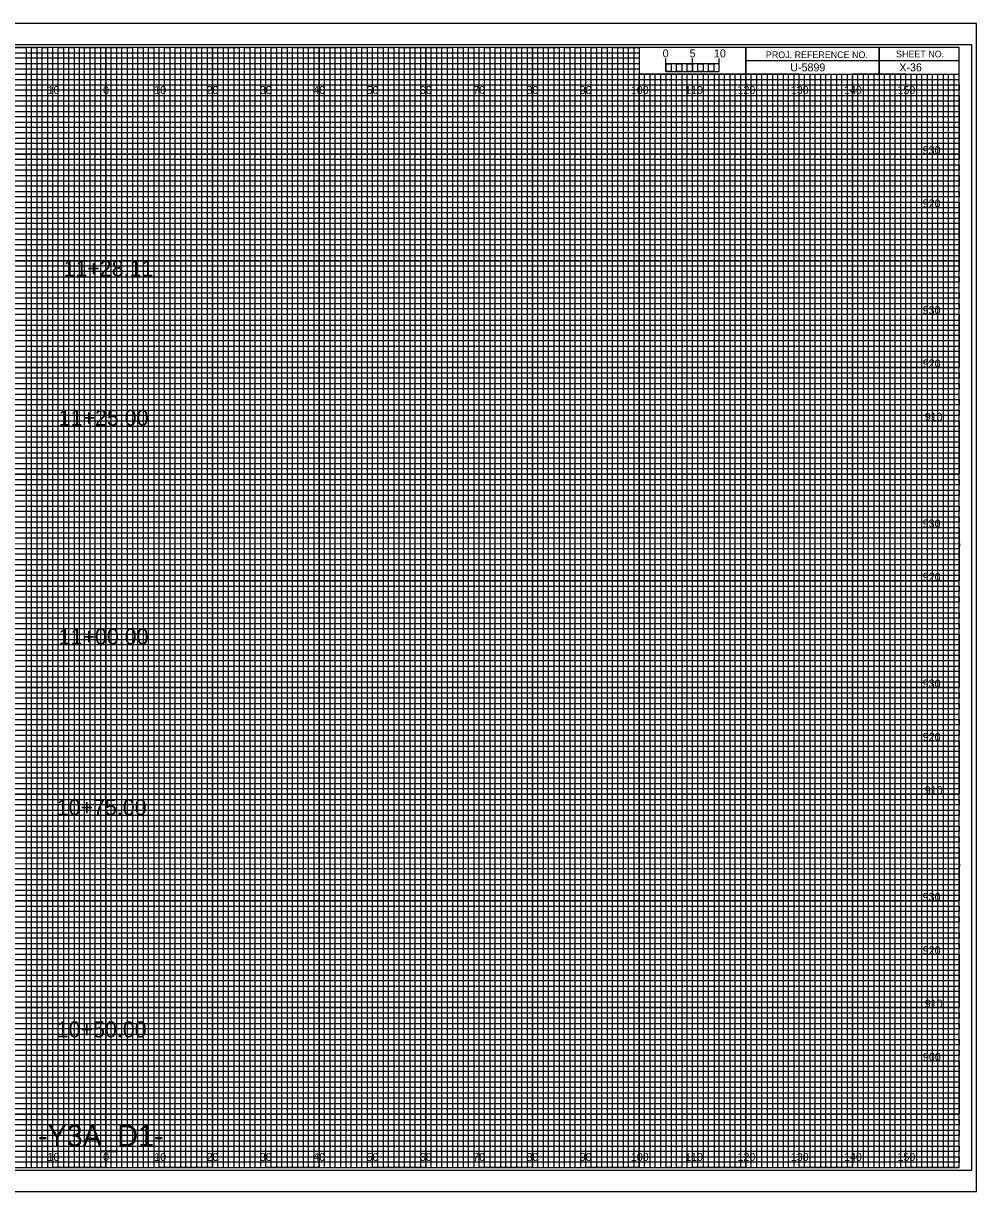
# Model space of a CAD drawing. Extents: x -13 to 323, y -4 to 214.
# Drawn here: x 144.5 to 323.3, y -4.5 to 214.5 of the extents above; entities that cross this region are included whole.
import ezdxf

# ---------------------------------------------------------------- set-up
doc = ezdxf.new("R2010")
doc.units = 0
for name, color, linetype in [('Prop XS Alignment Label', 7, 'Continuous'), ('Prop XS Bar Scale Labels', 7, 'Continuous'), ('Prop XS Elevation Labels', 7, 'Continuous'), ('Prop XS Offset Labels', 7, 'Continuous'), ('Prop XS Project Number', 7, 'Continuous'), ('Prop XS Sheet Number', 7, 'Continuous'), ('Prop XS Station Labels', 7, 'Continuous'), ('Sheet Cross Section CELL', 7, 'Continuous'), ('Sheet Cross Section Grid Major CELL', 7, 'Continuous'), ('Sheet Cross Section Grid Middle CELL', 7, 'Continuous'), ('Sheet Cross Section Grid Minor 1 CELL', 7, 'Continuous'), ('Sheet Cross Section Grid Minor 2 CELL', 7, 'Continuous'), ('Sheet Cross Section Scale CELL', 7, 'Continuous'), ('Sheet Cutting Line CELL', 7, 'Continuous'), ('Sheet DOT Grid CELL', 7, 'Continuous'), ('Sheet Plot Border Inside CELL', 7, 'Continuous'), ('Sheet Plot Border Outside CELL', 7, 'Continuous')]:
    doc.layers.add(name, color=color, linetype=linetype)

msp = doc.modelspace()

# ---------------------------------------------------------------- linework, layer by layer
at = {"layer": 'Sheet Cross Section CELL'}
for p, q in [((305, 210), (305, 205)), ((305, 205), (305, 210)), ((280, 207.5), (280, 205)), ((320, 207.49), (280, 207.49)), ((280, 205), (320, 205))]:
    msp.add_line(p, q, dxfattribs=at)
for points in [[(320, 210), (0, 210), (0, 0), (320, 0)], [(280, 210), (260, 210), (260, 205.03), (280, 205.03)], [(320, 210), (280, 210), (280, 205), (320, 205)]]:
    msp.add_lwpolyline(points, close=True, dxfattribs=at)
at = {"layer": 'Sheet Cross Section Grid Major CELL'}
for p, q in [((150, 210), (140, 210)), ((150, 0), (150, 210)), ((170, 210), (160, 210)), ((160, 210), (160, 0)), ((170, 0), (170, 210)), ((190, 210), (180, 210)), ((180, 210), (180, 0)), ((190, 0), (190, 210)), ((210, 210), (200, 210)), ((200, 210), (200, 0)), ((210, 0), (210, 210)), ((230, 210), (220, 210)), ((220, 210), (220, 0)), ((230, 0), (230, 210)), ((250, 210), (240, 210)), ((240, 210), (240, 0)), ((250, 0), (250, 210)), ((260, 210), (260, 0)), ((270, 0), (270, 205)), ((290, 205), (280, 205)), ((280, 205), (280, 0)), ((290, 0), (290, 205)), ((310, 205), (300, 205)), ((300, 205), (300, 0)), ((310, 0), (310, 205)), ((160, 0), (150, 0)), ((180, 0), (170, 0)), ((200, 0), (190, 0)), ((220, 0), (210, 0)), ((240, 0), (230, 0)), ((260, 0), (250, 0)), ((280, 0), (270, 0)), ((300, 0), (290, 0)), ((320, 0), (310, 0)), ((320, 0), (320, 0))]:
    msp.add_line(p, q, dxfattribs=at)
for points in [[(0, 200), (320, 200), (320, 190), (0, 190)], [(0, 180), (320, 180), (320, 170), (0, 170)], [(0, 160), (320, 160), (320, 150), (0, 150)], [(0, 140), (320, 140), (320, 130), (0, 130)], [(0, 120), (320, 120), (320, 110), (0, 110)], [(0, 100), (320, 100), (320, 90), (0, 90)], [(0, 80), (320, 80), (320, 70), (0, 70)], [(0, 60), (320, 60), (320, 50), (0, 50)], [(0, 40), (320, 40), (320, 30), (0, 30)], [(0, 20), (320, 20), (320, 10), (0, 10)]]:
    msp.add_lwpolyline(points, dxfattribs=at)
at = {"layer": 'Sheet Cross Section Grid Middle CELL'}
for points in [[(135, 210), (145, 210), (145, 0), (155, 0), (155, 210), (165, 210), (165, 0), (175, 0), (175, 210), (185, 210), (185, 0), (195, 0), (195, 210), (205, 210), (205, 0), (215, 0), (215, 210), (225, 210), (225, 0), (235, 0), (235, 210), (245, 210), (245, 0), (255, 0), (255, 210), (259.93, 210), (260, 210), (260, 205), (264.99, 205), (264.99, 0), (275, 0), (275, 205), (285, 205), (285, 0), (295, 0), (295, 205), (305, 205), (305, 0), (315, 0), (315, 205)], [(0, 205), (275, 205)], [(0, 185), (320, 185), (320, 195), (0, 195)], [(0, 165), (320, 165), (320, 175), (0, 175)], [(0, 145), (320, 145), (320, 155), (0, 155)], [(0, 125), (320, 125), (320, 135), (0, 135)], [(0, 105), (320, 105), (320, 115), (0, 115)], [(0, 85), (320, 85), (320, 95), (0, 95)], [(0, 65), (320, 65), (320, 75), (0, 75)], [(0, 45), (320, 45), (320, 55), (0, 55)], [(0, 25), (320, 25), (320, 35), (0, 35)], [(0, 5), (320, 5), (320, 15), (0, 15)]]:
    msp.add_lwpolyline(points, dxfattribs=at)
at = {"layer": 'Sheet Cross Section Grid Minor 1 CELL'}
for p, q in [((0, 209), (260, 209)), ((260, 209), (260, 207.98)), ((260, 207.98), (0, 207.98)), ((0, 207), (260, 207)), ((260, 205.89), (0, 205.89)), ((260, 207), (260, 205.89)), ((0, 204), (320, 204))]:
    msp.add_line(p, q, dxfattribs=at)
for points in [[(0, 203), (270, 203), (320, 203), (320, 202), (0, 202)], [(0, 201), (320, 201), (320, 199), (0, 199)], [(0, 198), (320, 198), (320, 197), (0, 196.98)], [(0, 196), (320, 196), (320, 194), (0, 194)], [(0, 193), (320, 193), (320, 192), (0, 192)], [(0, 191), (320, 191), (320, 189), (0, 189)], [(0, 188), (320, 188), (320, 187), (0, 187)], [(0, 186), (320, 186), (320, 184), (0, 184)], [(0, 183), (320, 183), (320, 182), (0, 182)], [(0, 181), (320, 181), (320, 179), (0, 179)], [(0, 178), (320, 178), (320, 177), (0, 177)], [(0, 176), (320, 176), (320, 173.95), (320, 173), (320, 172), (0, 172)], [(0, 174), (320, 174), (320, 173), (0, 173)], [(0, 171), (320, 171), (320, 169), (0, 169.03)], [(0, 169.03), (320, 169), (320, 168), (0, 168)], [(0, 167), (320, 167), (320, 166), (0, 166)], [(0, 164), (320, 164), (320, 163), (0, 163)], [(0, 162), (320, 162), (320, 161), (0, 161)], [(-0.07, 158.89), (320, 158.89), (320, 157.88), (-0.07, 157.88)], [(0, 157), (320, 157), (320, 156), (0, 156)], [(0, 154), (320, 154), (320, 153), (0, 153)], [(0, 152), (320, 152), (320, 151), (0, 151)], [(0, 149), (320, 149), (320, 148), (0, 148)], [(0, 147), (320, 147), (320, 146), (0, 146)], [(0, 144), (320, 144), (320, 143), (0, 143)], [(0, 142), (320, 142), (320, 141), (0, 141)], [(0, 139), (320, 139), (319.99, 137.98), (0, 138)], [(0, 137), (320, 137), (320, 136), (0, 136)], [(0, 134), (320, 134), (320, 133), (0, 133)], [(0, 132), (320, 132), (320, 131), (0, 131)], [(0, 129), (320, 129), (320, 128), (0, 128)], [(0, 127), (320, 127), (320, 126), (0, 126)], [(0, 124), (320, 124), (320, 123), (0, 123)], [(0, 122), (320, 122), (320, 121), (0, 121)], [(0, 119), (320, 119), (320, 118), (0, 118)], [(0, 116.99), (320.07, 116.91), (320, 116), (0, 116)], [(0, 114), (320, 114), (320, 113), (0, 113)], [(0, 112), (320, 112), (320, 111), (0, 111)], [(0, 109), (320, 109), (320, 108), (0, 108)], [(0, 107), (320, 107), (320, 106), (0, 106)], [(0, 104), (320, 104), (320, 103), (0, 103)], [(0, 102), (320, 102), (320, 101), (0, 101)], [(0, 99), (320, 99), (320, 98), (0, 98)], [(0, 97), (320, 97), (320, 96), (0, 96)], [(0, 94), (320, 94), (320, 93), (0, 93)], [(0, 92), (320, 92), (320, 91), (0, 91)], [(0, 89), (320, 89), (320, 88), (0, 88)], [(0, 87), (320, 87), (320, 86), (0, 86)], [(0, 84), (320, 84), (320, 83), (0, 83)], [(0, 82), (320, 82), (320, 81), (0, 81)], [(0, 79), (320, 79), (319.99, 77.98), (0, 78)], [(0, 77), (320, 77), (320, 76), (0, 76)], [(0, 74), (320, 74), (320, 73), (0, 73)], [(0, 72), (320, 72), (320, 71), (0, 71)], [(0, 69), (320, 69), (320, 68), (0, 68)], [(0, 67), (320, 67), (320, 66), (0, 66)], [(0, 64), (320, 64), (320, 63), (0, 63)], [(0, 62), (320, 62), (320, 61), (0, 61)], [(0, 59), (320, 59), (320, 58), (0, 58)], [(0, 56.99), (320.07, 56.91), (320, 56), (0, 56)], [(0, 54), (320, 54), (320, 53), (0, 53)], [(0, 52), (320, 52), (320, 51), (0, 51)], [(0, 49), (320, 49), (320, 48), (0, 48)], [(0, 47), (320, 47), (320, 46), (0, 46)], [(0, 44), (320, 44), (320, 43), (0, 43)], [(0, 42), (320, 42), (320, 41), (0, 41)], [(0, 39), (320, 39), (320, 38), (0, 38)], [(0, 37), (320, 37), (320, 36), (0, 36)], [(0, 34), (320, 34), (320, 33), (0, 33)], [(0, 32), (320, 32), (320, 31), (0, 31)], [(0, 29), (320, 29), (320, 28), (0, 28)], [(0, 27), (320, 27), (320, 26), (0, 26)], [(0, 24), (320, 24), (320, 23), (0, 23)], [(0, 22), (320, 22), (320, 21), (0, 21)], [(0, 19), (320, 19), (320, 18), (0, 18)], [(0, 17), (320, 17), (320, 16), (0, 16)], [(0, 14), (320, 14), (320, 13), (0, 13)], [(0, 12), (320, 12), (320, 11), (0, 11)], [(0, 9), (320, 9), (320, 8), (0, 8)], [(0, 7), (320, 7), (320, 6), (0, 6)], [(0, 4), (320, 4), (320, 3), (0, 3)], [(0, 2), (320, 2), (320, 1), (0, 1)]]:
    msp.add_lwpolyline(points, dxfattribs=at)
at = {"layer": 'Sheet Cross Section Grid Minor 2 CELL'}
for p, q in [((267, 205), (266.01, 205)), ((266.01, 205), (266.01, 0)), ((267, 0), (267, 205)), ((269, 205), (268, 205)), ((268, 205), (268, 0)), ((269, 0), (269, 205)), ((266.01, 0), (265, 0)), ((268, 0), (267, 0))]:
    msp.add_line(p, q, dxfattribs=at)
for points in [[(145, 0), (146, 0), (146, 210), (147, 210), (147, 0)], [(147, 0), (148, 0), (148, 210), (149, 210), (149, 0)], [(150, 0), (151, 0), (151, 210), (152, 210), (152, 0)], [(152, 0), (153, 0), (153, 210), (154, 210), (154, 0)], [(155, 0), (156, 0), (156, 210), (157, 210), (157, 0)], [(157, 0), (158, 0), (158, 210), (159, 210), (159, 0)], [(160, 0), (161, 0), (161, 210), (162, 210), (162, 0)], [(162, 0), (163, 0), (163, 210), (164, 210), (164, 0)], [(165, 0), (166, 0), (166, 210), (167, 210), (167, 0)], [(167, 0), (168, 0), (168, 210), (169, 210), (169, 0)], [(170, 0), (171, 0), (171, 210), (172, 210), (172, 0)], [(172, 0), (173, 0), (173, 210), (174, 210), (174, 0)], [(175, 0), (176, 0), (176, 210), (177, 210), (177, 0)], [(177, 0), (178, 0), (178, 210), (179, 210), (179, 0)], [(180, 0), (181, 0), (181, 210), (182, 210), (182, 0)], [(182, 0), (183, 0), (183, 210), (184, 210), (184, 0)], [(185, 0), (186, 0), (186, 210), (187, 210), (187, 0)], [(187, 0), (188, 0), (188, 210), (189, 210), (189, 0)], [(190, 0), (191, 0), (191, 210), (192, 210), (192, 0)], [(192, 0), (193, 0), (193, 210), (194, 210), (194, 0)], [(195, 0), (196, 0), (196, 210), (197, 210), (197, 0)], [(197, 0), (198, 0), (198, 210), (199, 210), (199, 0)], [(200, 0), (201, 0), (201, 210), (202, 210), (202, 0)], [(202, 0), (203, 0), (203, 210), (204, 210), (204, 0)], [(205, 0), (206, 0), (206, 210), (207, 210), (207, 0)], [(207, 0), (208, 0), (208, 210), (209, 210), (209, 0)], [(210, 0), (211, 0), (211, 210), (212, 210), (212, 0)], [(212, 0), (213, 0), (213, 210), (214, 210), (214, 0)], [(215, 0), (216, 0), (216, 210), (217, 210), (217, 0)], [(217, 0), (218, 0), (218, 210), (219, 210), (219, 0)], [(220, 0), (221, 0), (221, 210), (222, 210), (222, 0)], [(222, 0), (223, 0), (223, 210), (224, 210), (224, 0)], [(225, 0), (226, 0), (226, 210), (227, 210), (227, 0)], [(227, 0), (228, 0), (228, 210), (229, 210), (229, 0)], [(230, 0), (231, 0), (231, 210), (232, 210), (232, 0)], [(232, 0), (233, 0), (233, 210), (234, 210), (234, 0)], [(235, 0), (236, 0), (236, 210), (237, 210), (237, 0)], [(237, 0), (238, 0), (238, 210), (239, 210), (239, 0)], [(240, 0), (241, 0), (241, 210), (242, 210), (242, 0)], [(242, 0), (243, 0), (243, 210), (244, 210), (244, 0)], [(245, 0), (246, 0), (246, 210), (247, 210), (247, 0)], [(247, 0), (248, 0), (248, 210), (249, 210), (249, 0)], [(250, 0), (251, 0), (251, 210), (252, 210), (252, 0)], [(252, 0), (253, 0), (253, 210), (254, 210), (254, 0)], [(255, 0), (256, 0), (256, 210), (257, 210), (257, 0)], [(257, 0), (258, 0), (258, 210), (259, 210), (259, 0)], [(260, 0), (261, 0), (261, 205), (262.02, 205), (262.02, 0)], [(262, 0), (263, 0), (263, 205), (263.99, 205), (263.99, 0)], [(270, 0), (270.98, 0), (270.98, 205), (272, 205), (272, 0)], [(272, 0), (273, 0), (273, 205), (274.05, 205), (274.05, 0)], [(275, 0), (276, 0), (276, 205), (277, 205), (277, 0)], [(277, 0), (278, 0), (278, 205), (279, 205), (279, 0)], [(280, 0), (281, 0), (281, 205), (282, 205), (282, 0)], [(282, 0), (283, 0), (283, 205), (284, 205), (284, 0)], [(285, 0), (286, 0), (286, 205), (287, 205), (287, 0)], [(287, 0), (288, 0), (288, 205), (289, 205), (289, 0)], [(290, 0), (291, 0), (291, 205), (292, 205), (292, 0)], [(292, 0), (293, 0), (293, 205), (294, 205), (294, 0)], [(295, 0), (296, 0), (296, 205), (297, 205), (297, 0)], [(297, 0), (298, 0), (298, 205), (299, 205), (299, 0)], [(300, 0), (301, 0), (301, 205), (302, 205), (302, 0)], [(302, 0), (303, 0), (303, 205), (304, 205), (304, 0)], [(305, 0), (306, 0), (306, 205), (307, 205), (307, 0)], [(307, 0), (308, 0), (308, 205), (309, 205), (309, 0)], [(310, 0), (311, 0), (311, 205), (312, 205), (312, 0)], [(312, 0), (313, 0), (313, 205), (314, 205), (314, 0)], [(315, 0), (316, 0), (316, 205), (317, 205), (317, 0)], [(317, 0), (318, 0), (318, 205), (319, 205), (319, 0)]]:
    msp.add_lwpolyline(points, dxfattribs=at)
at = {"layer": 'Sheet Cross Section Scale CELL'}
for p, q in [((265, 205.49), (265, 207.9)), ((265, 206.9), (265, 207.9)), ((270, 205.49), (270, 207.9)), ((275, 205.49), (275, 207.9)), ((275, 206.9), (275, 207.9))]:
    msp.add_line(p, q, dxfattribs=at)
for points in [[(275, 206.9), (265, 206.9), (265, 205.49), (275, 205.49)], [(265, 206.9), (266, 206.9), (266, 205.49), (265, 205.49)], [(267, 206.9), (268, 206.9), (268, 205.49), (267, 205.49)], [(269, 206.9), (270, 206.9), (270, 205.49), (269, 205.49)], [(271, 206.9), (272, 206.9), (272, 205.49), (271, 205.49)], [(273, 206.9), (274, 206.9), (274, 205.49), (273, 205.49)]]:
    msp.add_lwpolyline(points, close=True, dxfattribs=at)
at = {"layer": 'Sheet Cutting Line CELL'}
for p, q in [((323.3, 214.5), (-13.4, 214.5)), ((-13.4, -4.5), (323.3, -4.5))]:
    msp.add_line(p, q, dxfattribs=at)
at = {"layer": 'Sheet DOT Grid CELL'}
for p, q in [((150, 0), (150, 210)), ((160, 0), (160, 210)), ((170, 0), (170, 210)), ((180, 0), (180, 210)), ((190, 0), (190, 210)), ((200, 0), (200, 210)), ((210, 0), (210, 210)), ((220, 0), (220, 210)), ((230, 0), (230, 210)), ((240, 0), (240, 210)), ((250, 0), (250, 210)), ((260, 0), (260, 204.69)), ((270, 0), (270, 204.69)), ((280, 0), (280, 204.69)), ((290, 0), (290, 204.69)), ((300, 0), (300, 204.69)), ((310, 0), (310, 204.69)), ((0, 200), (320, 200)), ((0, 190), (320, 190)), ((0, 180), (320, 180)), ((0, 170), (320, 170)), ((0, 160), (320, 160)), ((0, 150), (320, 150)), ((0, 140), (320, 140)), ((0, 130), (320, 130)), ((0, 120), (320, 120)), ((0, 110), (320, 110)), ((0, 100), (320, 100)), ((0, 90), (320, 90)), ((0, 80), (320, 80)), ((0, 70), (320, 70)), ((0, 60), (320, 60)), ((0, 50), (320, 50)), ((0, 40), (320, 40)), ((0, 30), (320, 30)), ((0, 20), (320, 20)), ((0, 10), (320, 10))]:
    msp.add_line(p, q, dxfattribs=at)
at = {"layer": 'Sheet Plot Border Inside CELL'}
msp.add_lwpolyline([(-10.8, -0.5), (322.4, -0.5), (322.4, 210.5), (-10.8, 210.5)], close=True, dxfattribs=at)
at = {"layer": 'Sheet Plot Border Outside CELL'}
msp.add_lwpolyline([(-13.4, -4.5), (323.3, -4.5), (323.3, 214.5), (-13.4, 214.5)], close=True, dxfattribs=at)

# ---------------------------------------------------------------- texts
at = {"layer": 'Prop XS Alignment Label'}
msp.add_text('-Y3A_D1-', height=4, dxfattribs=at).set_placement((147.29, 4))
at = {"layer": 'Prop XS Bar Scale Labels'}
for s, p in [('5', (269.47, 208.12)), ('10', (274.04, 208.12))]:
    msp.add_text(s, height=1.5, dxfattribs=at).set_placement(p)
at = {"layer": 'Prop XS Elevation Labels'}
for s, p in [('930', (313.18, 190)), ('920', (313.19, 180)), ('930', (313.18, 160)), ('920', (313.19, 150)), ('910', (313.57, 140)), ('930', (313.18, 120)), ('920', (313.19, 110)), ('930', (313.18, 90)), ('920', (313.19, 80)), ('910', (313.57, 70)), ('930', (313.18, 50)), ('920', (313.19, 40)), ('910', (313.57, 30)), ('900', (313.24, 20))]:
    msp.add_text(s, height=1.5, dxfattribs=at).set_placement(p)
at = {"layer": 'Prop XS Offset Labels'}
for s, p in [('10', (149.04, 201.25)), ('0', (159.45, 201.25)), ('0', (159.45, 201.25)), ('10', (169.04, 201.25)), ('20', (178.86, 201.25)), ('30', (188.86, 201.25)), ('40', (198.86, 201.25)), ('50', (208.86, 201.25)), ('60', (218.86, 201.25)), ('70', (228.86, 201.25)), ('80', (238.86, 201.25)), ('90', (248.86, 201.25)), ('100', (258.44, 201.25)), ('110', (268.62, 201.25)), ('120', (278.44, 201.25)), ('130', (288.44, 201.25)), ('140', (298.44, 201.25)), ('150', (308.44, 201.25)), ('10', (149.04, 1.25)), ('0', (159.45, 1.25)), ('0', (159.45, 1.25)), ('10', (169.04, 1.25)), ('20', (178.86, 1.25)), ('30', (188.86, 1.25)), ('40', (198.86, 1.25)), ('50', (208.86, 1.25)), ('60', (218.86, 1.25)), ('70', (228.86, 1.25)), ('80', (238.86, 1.25)), ('90', (248.86, 1.25)), ('100', (258.44, 1.25)), ('110', (268.62, 1.25)), ('120', (278.44, 1.25)), ('130', (288.44, 1.25)), ('140', (298.44, 1.25)), ('150', (308.44, 1.25))]:
    msp.add_text(s, height=1.5, dxfattribs=at).set_placement(p)
at = {"layer": 'Prop XS Project Number'}
msp.add_text('U-5899', height=1.5, dxfattribs=at).set_placement((288.34, 205.5))
at = {"layer": 'Prop XS Sheet Number'}
msp.add_text('X-36', height=1.5, dxfattribs=at).set_placement((308.8, 205.5))
at = {"layer": 'Prop XS Station Labels'}
for s, p in [('11+28.11', (152.04, 167.08)), ('11+25.00', (151.13, 139.08)), ('11+00.00', (151.13, 98.07)), ('10+75.00', (150.77, 66.05)), ('10+50.00', (150.77, 24.42))]:
    msp.add_text(s, height=3, dxfattribs=at).set_placement(p)
at = {"layer": 'Sheet Cross Section CELL'}
for s, p in [('PROJ. REFERENCE NO.', (283.77, 207.99)), ('SHEET NO.', (308.19, 208.12))]:
    msp.add_text(s, height=1.25, dxfattribs=at).set_placement(p)
at = {"layer": 'Sheet Cross Section Scale CELL'}
msp.add_text('0', height=1.5, dxfattribs=at).set_placement((264.41, 208.12))

doc.saveas('drawing.dxf')
